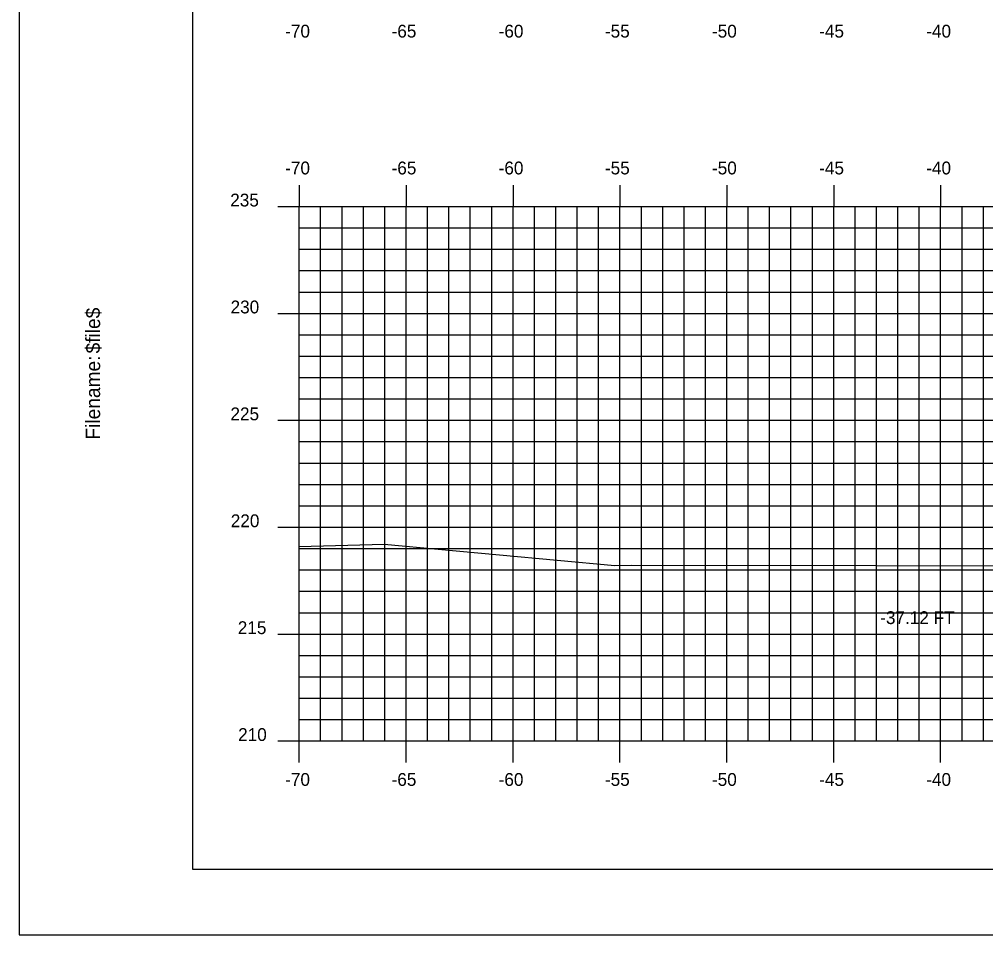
# Model space of a CAD drawing. Extents: x 1137654 to 1137824, y 608981 to 609091.
# Drawn here: x 1137654.32 to 1137699.51, y 608981.28 to 609024.09 of the extents above; entities that cross this region are included whole.
import ezdxf

# ---------------------------------------------------------------- set-up
doc = ezdxf.new("R2010")
doc.units = 0
for name, color, linetype in [('BORDER', 7, 'Continuous'), ('D_Text_Standard', 7, 'Continuous'), ('H_V ANNOTATION', 7, 'Continuous'), ('MAJOR', 7, 'Continuous'), ('MINOR', 7, 'Continuous'), ('PLOT BOUNDARY', 7, 'Continuous'), ('S_Roadway_Centerline', 7, 'Continuous')]:
    doc.layers.add(name, color=color, linetype=linetype)

msp = doc.modelspace()

# ---------------------------------------------------------------- linework, layer by layer
at = {"layer": 'BORDER'}
msp.add_lwpolyline([(1137662.41, 608984.335), (1137822.41, 608984.335), (1137822.41, 609089.335), (1137662.41, 609089.335)], close=True, dxfattribs=at)
at = {"layer": 'MAJOR'}
for p, q in [((1137667.409, 609016.337), (1137667.409, 609015.335)), ((1137672.409, 609016.337), (1137672.409, 609015.335)), ((1137677.409, 609016.337), (1137677.409, 609015.335)), ((1137682.409, 609016.337), (1137682.409, 609015.335)), ((1137687.409, 609016.337), (1137687.409, 609015.335)), ((1137692.409, 609016.337), (1137692.409, 609015.335)), ((1137697.409, 609016.337), (1137697.409, 609015.335)), ((1137666.407, 609015.335), (1137667.409, 609015.335)), ((1137667.409, 609015.335), (1137807.409, 609015.335)), ((1137667.409, 608990.335), (1137667.409, 609015.335)), ((1137667.409, 608990.335), (1137667.409, 609015.335)), ((1137667.409, 609015.335), (1137807.409, 609015.335)), ((1137672.409, 608990.335), (1137672.409, 609015.335)), ((1137677.409, 608990.335), (1137677.409, 609015.335)), ((1137682.409, 608990.335), (1137682.409, 609015.335)), ((1137687.409, 608990.335), (1137687.409, 609015.335)), ((1137692.409, 608990.335), (1137692.409, 609015.335)), ((1137697.409, 608990.335), (1137697.409, 609015.335)), ((1137666.407, 609010.335), (1137667.409, 609010.335)), ((1137667.409, 609010.335), (1137807.409, 609010.335)), ((1137666.407, 609005.335), (1137667.409, 609005.335)), ((1137667.409, 609005.335), (1137807.409, 609005.335)), ((1137666.407, 609000.335), (1137667.409, 609000.335)), ((1137667.409, 609000.335), (1137807.409, 609000.335)), ((1137666.407, 608995.335), (1137667.409, 608995.335)), ((1137667.409, 608995.335), (1137807.409, 608995.335)), ((1137666.407, 608990.335), (1137667.409, 608990.335)), ((1137667.409, 608990.335), (1137807.409, 608990.335)), ((1137667.409, 608990.335), (1137807.409, 608990.335)), ((1137667.409, 608989.333), (1137667.409, 608990.335)), ((1137672.409, 608989.333), (1137672.409, 608990.335)), ((1137677.409, 608989.333), (1137677.409, 608990.335)), ((1137682.409, 608989.333), (1137682.409, 608990.335)), ((1137687.409, 608989.333), (1137687.409, 608990.335)), ((1137692.409, 608989.333), (1137692.409, 608990.335)), ((1137697.409, 608989.333), (1137697.409, 608990.335))]:
    msp.add_line(p, q, dxfattribs=at)
at = {"layer": 'MINOR'}
for p, q in [((1137668.409, 608990.335), (1137668.409, 609015.335)), ((1137669.409, 608990.335), (1137669.409, 609015.335)), ((1137670.409, 608990.335), (1137670.409, 609015.335)), ((1137671.409, 608990.335), (1137671.409, 609015.335)), ((1137673.409, 608990.335), (1137673.409, 609015.335)), ((1137674.409, 608990.335), (1137674.409, 609015.335)), ((1137675.409, 608990.335), (1137675.409, 609015.335)), ((1137676.409, 608990.335), (1137676.409, 609015.335)), ((1137678.409, 608990.335), (1137678.409, 609015.335)), ((1137679.409, 608990.335), (1137679.409, 609015.335)), ((1137680.409, 608990.335), (1137680.409, 609015.335)), ((1137681.409, 608990.335), (1137681.409, 609015.335)), ((1137683.409, 608990.335), (1137683.409, 609015.335)), ((1137684.409, 608990.335), (1137684.409, 609015.335)), ((1137685.409, 608990.335), (1137685.409, 609015.335)), ((1137686.409, 608990.335), (1137686.409, 609015.335)), ((1137688.409, 608990.335), (1137688.409, 609015.335)), ((1137689.409, 608990.335), (1137689.409, 609015.335)), ((1137690.409, 608990.335), (1137690.409, 609015.335)), ((1137691.409, 608990.335), (1137691.409, 609015.335)), ((1137693.409, 608990.335), (1137693.409, 609015.335)), ((1137694.409, 608990.335), (1137694.409, 609015.335)), ((1137695.409, 608990.335), (1137695.409, 609015.335)), ((1137696.409, 608990.335), (1137696.409, 609015.335)), ((1137698.409, 608990.335), (1137698.409, 609015.335)), ((1137699.409, 608990.335), (1137699.409, 609015.335)), ((1137667.409, 609014.335), (1137807.409, 609014.335)), ((1137667.409, 609014.335), (1137668.411, 609014.335)), ((1137667.409, 609013.335), (1137807.409, 609013.335)), ((1137667.409, 609013.335), (1137668.411, 609013.335)), ((1137667.409, 609012.335), (1137807.409, 609012.335)), ((1137667.409, 609012.335), (1137668.411, 609012.335)), ((1137667.409, 609011.335), (1137807.409, 609011.335)), ((1137667.409, 609011.335), (1137668.411, 609011.335)), ((1137667.409, 609009.335), (1137807.409, 609009.335)), ((1137667.409, 609009.335), (1137668.411, 609009.335)), ((1137667.409, 609008.335), (1137807.409, 609008.335)), ((1137667.409, 609008.335), (1137668.411, 609008.335)), ((1137667.409, 609007.335), (1137807.409, 609007.335)), ((1137667.409, 609007.335), (1137668.411, 609007.335)), ((1137667.409, 609006.335), (1137807.409, 609006.335)), ((1137667.409, 609006.335), (1137668.411, 609006.335)), ((1137667.409, 609004.335), (1137807.409, 609004.335)), ((1137667.409, 609004.335), (1137668.411, 609004.335)), ((1137667.409, 609003.335), (1137807.409, 609003.335)), ((1137667.409, 609003.335), (1137668.411, 609003.335)), ((1137667.409, 609002.335), (1137807.409, 609002.335)), ((1137667.409, 609002.335), (1137668.411, 609002.335)), ((1137667.409, 609001.335), (1137807.409, 609001.335)), ((1137667.409, 609001.335), (1137668.411, 609001.335)), ((1137667.409, 608999.335), (1137807.409, 608999.335)), ((1137667.409, 608999.335), (1137668.411, 608999.335)), ((1137667.409, 608998.335), (1137807.409, 608998.335)), ((1137667.409, 608998.335), (1137668.411, 608998.335)), ((1137667.409, 608997.335), (1137807.409, 608997.335)), ((1137667.409, 608997.335), (1137668.411, 608997.335)), ((1137667.409, 608996.335), (1137807.409, 608996.335)), ((1137667.409, 608996.335), (1137668.411, 608996.335)), ((1137667.409, 608994.335), (1137807.409, 608994.335)), ((1137667.409, 608994.335), (1137668.411, 608994.335)), ((1137667.409, 608993.335), (1137807.409, 608993.335)), ((1137667.409, 608993.335), (1137668.411, 608993.335)), ((1137667.409, 608992.335), (1137807.409, 608992.335)), ((1137667.409, 608992.335), (1137668.411, 608992.335)), ((1137667.409, 608991.335), (1137807.409, 608991.335)), ((1137667.409, 608991.335), (1137668.411, 608991.335))]:
    msp.add_line(p, q, dxfattribs=at)
at = {"layer": 'PLOT BOUNDARY'}
msp.add_lwpolyline([(1137654.316, 608981.276), (1137824.316, 608981.276), (1137824.316, 609091.276), (1137654.316, 609091.276)], close=True, dxfattribs=at)
at = {"layer": 'S_Roadway_Centerline'}
msp.add_lwpolyline([(1137667.409, 608999.427), (1137671.375, 608999.533), (1137682.176, 608998.539), (1137682.929, 608998.559), (1137705.808, 608998.523), (1137708.965, 608998.916), (1137713.914, 609000.539), (1137720.407, 609004.41), (1137723.296, 609004.805), (1137723.932, 609004.904), (1137726.625, 609004.961), (1137735.098, 609005.026), (1137742.791, 609004.952), (1137745.524, 609004.989), (1137745.621, 609004.875), (1137747.251, 609004.35), (1137748.161, 609004.238), (1137757.699, 609001.458), (1137758.717, 609001.317), (1137759.74, 609001.407), (1137760.775, 609001.568), (1137762.91, 609002.502), (1137768.911, 609004.157)], dxfattribs=at)

# ---------------------------------------------------------------- texts
at = {"layer": 'BORDER'}
for s, p in [('$file$', (1137658.095, 609008.461)), ('Filename:', (1137658.095, 609004.433))]:
    msp.add_text(s, height=0.6696, rotation=90, dxfattribs=at).set_placement(p)
at = {"layer": 'D_Text_Standard'}
msp.add_text('-37.12 FT', height=0.6, dxfattribs=at).set_placement((1137694.582, 608995.805))
at = {"layer": 'H_V ANNOTATION'}
for s, p in [('-70', (1137666.751, 609023.235)), ('-65', (1137671.727, 609023.235)), ('-60', (1137676.735, 609023.235)), ('-55', (1137681.706, 609023.235)), ('-50', (1137686.714, 609023.235)), ('-45', (1137691.727, 609023.235)), ('-40', (1137696.735, 609023.235)), ('-70', (1137666.751, 609016.835)), ('-65', (1137671.727, 609016.835)), ('-60', (1137676.735, 609016.835)), ('-55', (1137681.706, 609016.835)), ('-50', (1137686.714, 609016.835)), ('-45', (1137691.727, 609016.835)), ('-40', (1137696.735, 609016.835)), ('235', (1137664.181, 609015.335)), ('230', (1137664.197, 609010.335)), ('225', (1137664.191, 609005.335)), ('220', (1137664.207, 609000.335)), ('215', (1137664.534, 608995.335)), ('210', (1137664.55, 608990.335)), ('-70', (1137666.751, 608988.235)), ('-65', (1137671.727, 608988.235)), ('-60', (1137676.735, 608988.235)), ('-55', (1137681.706, 608988.235)), ('-50', (1137686.714, 608988.235)), ('-45', (1137691.727, 608988.235)), ('-40', (1137696.735, 608988.235))]:
    msp.add_text(s, height=0.6, dxfattribs=at).set_placement(p)
at = {"layer": 'MAJOR'}
msp.add_text('-', height=0.006, dxfattribs=at).set_placement((1137667.405, 608990.335))

doc.saveas('drawing.dxf')
